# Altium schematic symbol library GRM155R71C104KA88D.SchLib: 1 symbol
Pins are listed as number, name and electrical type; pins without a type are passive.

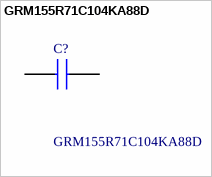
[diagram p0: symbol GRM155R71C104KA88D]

## GRM155R71C104KA88D
designator C?
Ceramic  SMT capacitor 100nF 16Vdc Murata 0402 GRM 100nF Ceramic Multilayer Capacitor, 16 V dc X7R Dielectric ??10%; Manufacturer_Name: Murata Electronics; Geometry.Height: 0.7mm
footprint CAPC1005X70N
pins: 1, 2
